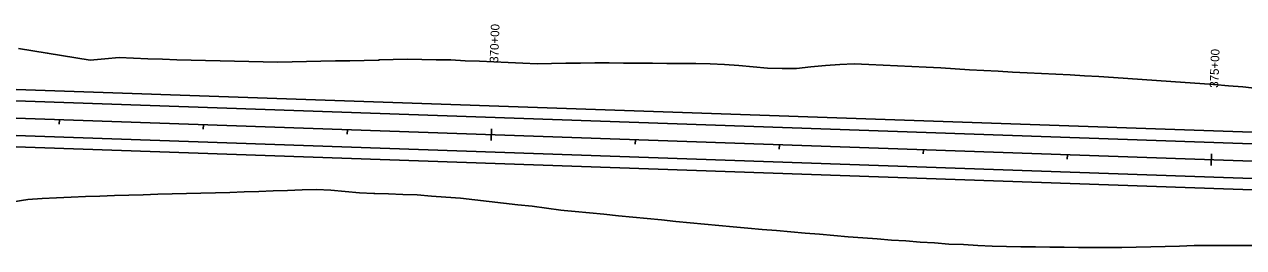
# Model space of a CAD drawing. Extents: x 881426 to 887360, y 1564404 to 1567430.
# Drawn here: x 885699 to 886545, y 1564418 to 1564573 of the extents above; entities that cross this region are included whole.
import ezdxf

# ---------------------------------------------------------------- set-up
doc = ezdxf.new("R2010")
doc.units = 0
for name, color, linetype in [('R_Horz Alg', 7, 'Continuous'), ('R_Horz Alg Annot', 7, 'Continuous'), ('R_Proposed Const Limits_Cut', 7, 'Continuous'), ('R_Proposed Const Limits_Fill', 7, 'Continuous'), ('R_Proposed Road_Lane', 7, 'Continuous'), ('R_Proposed Road_Shoulder', 7, 'Continuous')]:
    doc.layers.add(name, color=color, linetype=linetype)

msp = doc.modelspace()

# ---------------------------------------------------------------- linework, layer by layer
at = {"layer": 'R_Horz Alg'}
msp.add_line((885670.58, 1564508.69), (887357.73, 1564450.04), dxfattribs=at)
at = {"layer": 'R_Horz Alg Annot'}
for points in [[(885723.07, 1564503.86), (885723.17, 1564506.86)], [(885823.01, 1564500.39), (885823.11, 1564503.39)], [(885922.95, 1564496.91), (885923.05, 1564499.91)], [(886023.13, 1564500.43), (886022.85, 1564492.44)], [(886122.83, 1564489.96), (886122.93, 1564492.96)], [(886222.76, 1564486.49), (886222.87, 1564489.49)], [(886322.7, 1564483.02), (886322.81, 1564486.01)], [(886422.64, 1564479.54), (886422.75, 1564482.54)], [(886522.83, 1564483.06), (886522.55, 1564475.07)]]:
    msp.add_lwpolyline(points, dxfattribs=at)
at = {"layer": 'R_Proposed Const Limits_Cut'}
for points in [[(885744.62, 1564548.22), (885754.66, 1564549.23), (885764.69, 1564549.99), (885774.69, 1564549.57), (885784.68, 1564549.2), (885794.67, 1564548.85), (885804.67, 1564548.49), (885814.66, 1564548.2), (885824.66, 1564547.91), (885834.66, 1564547.67), (885844.65, 1564547.45), (885854.65, 1564547.22), (885864.65, 1564547.04), (885874.65, 1564546.94), (885884.67, 1564547.12), (885894.68, 1564547.31), (885904.69, 1564547.52), (885914.71, 1564547.72), (885924.72, 1564547.86), (885934.73, 1564548.02), (885944.75, 1564548.33), (885945.41, 1564548.35), (885954.76, 1564548.63), (885964.78, 1564548.94), (885974.78, 1564548.74), (885984.78, 1564548.54), (885994.78, 1564548.36), (886004.77, 1564547.88), (886014.76, 1564547.57), (886024.75, 1564547.13), (886034.74, 1564546.71), (886044.73, 1564546.22), (886054.72, 1564545.76), (886064.73, 1564545.84), (886074.74, 1564546.04), (886077.12, 1564546.07), (886084.76, 1564546.2), (886094.77, 1564546.33), (886104.77, 1564546.3), (886114.78, 1564546.24), (886124.78, 1564546.21), (886134.78, 1564546.14), (886144.79, 1564546.02), (886154.79, 1564545.95), (886164.79, 1564545.89), (886174.79, 1564545.64), (886184.78, 1564545.2), (886194.76, 1564544.41), (886204.74, 1564543.65), (886214.71, 1564542.68), (886224.71, 1564542.4), (886234.71, 1564542.38), (886244.76, 1564543.52), (886254.8, 1564544.47), (886264.83, 1564545.3), (886274.85, 1564545.69), (886284.84, 1564545.2), (886294.83, 1564544.79), (886304.82, 1564544.36), (886314.81, 1564543.81), (886324.8, 1564543.32), (886334.79, 1564542.81), (886344.77, 1564542.16), (886354.76, 1564541.58), (886364.75, 1564541.08), (886374.73, 1564540.48), (886384.72, 1564539.99), (886394.71, 1564539.54), (886404.7, 1564539.05), (886414.69, 1564538.55), (886424.68, 1564537.97), (886434.66, 1564537.35), (886444.65, 1564536.78), (886454.63, 1564536.19), (886464.61, 1564535.48), (886474.59, 1564534.78), (886484.58, 1564534.07), (886494.56, 1564533.41), (886504.54, 1564532.71), (886514.52, 1564531.98), (886524.5, 1564531.26), (886534.48, 1564530.5), (886544.46, 1564529.61), (886554.43, 1564528.56)], [(885901.59, 1564458.34), (885911.59, 1564457.94), (885921.56, 1564456.99), (885931.53, 1564456.04), (885941.52, 1564455.61), (885942.18, 1564455.59), (885951.52, 1564455.33), (885961.51, 1564454.94), (885971.5, 1564454.56), (885981.48, 1564453.77), (885991.46, 1564453.02), (886001.44, 1564452.25), (886011.41, 1564451.14), (886021.38, 1564450), (886031.34, 1564448.91), (886041.31, 1564447.78), (886051.28, 1564446.66), (886061.24, 1564445.37), (886071.2, 1564444.08), (886073.56, 1564443.79), (886081.17, 1564443.04), (886091.14, 1564442.06), (886101.11, 1564441.09), (886111.09, 1564440.11), (886121.06, 1564439.13), (886131.03, 1564438.16), (886141, 1564437.18), (886150.97, 1564436.2), (886160.95, 1564435.23), (886170.92, 1564434.25), (886180.89, 1564433.31), (886190.87, 1564432.4), (886200.84, 1564431.54), (886210.82, 1564430.64), (886220.79, 1564429.77), (886230.77, 1564428.9), (886240.74, 1564428.02), (886250.72, 1564427.19), (886260.7, 1564426.31), (886270.67, 1564425.49), (886280.65, 1564424.75), (886290.63, 1564424), (886300.61, 1564423.13), (886310.6, 1564422.58), (886320.57, 1564421.69), (886330.56, 1564421.22), (886340.54, 1564420.45), (886350.53, 1564420.01), (886360.52, 1564419.39), (886370.51, 1564418.94), (886380.51, 1564418.72), (886390.51, 1564418.59), (886400.51, 1564418.48), (886410.51, 1564418.33), (886420.51, 1564418.26), (886430.51, 1564418.1), (886440.52, 1564418.05), (886450.52, 1564417.93), (886460.53, 1564418.01), (886470.54, 1564418.15), (886480.56, 1564418.44), (886490.57, 1564418.77), (886500.59, 1564419.06), (886510.61, 1564419.37), (886520.61, 1564419.4), (886530.62, 1564419.35), (886540.62, 1564419.35), (886550.63, 1564419.33)]]:
    msp.add_lwpolyline(points, dxfattribs=at)
at = {"layer": 'R_Proposed Const Limits_Fill'}
for points in [[(885694.88, 1564556.43), (885704.82, 1564554.76), (885714.77, 1564553.14), (885724.72, 1564551.46), (885734.67, 1564549.75), (885744.62, 1564548.22)], [(885691.17, 1564449.84), (885701.23, 1564451.3), (885711.26, 1564452.13), (885721.28, 1564452.57), (885731.3, 1564452.99), (885741.32, 1564453.38), (885751.34, 1564453.71), (885761.36, 1564454.08), (885771.38, 1564454.42), (885781.4, 1564454.73), (885791.41, 1564455.06), (885801.43, 1564455.36), (885811.44, 1564455.61), (885821.46, 1564455.83), (885831.47, 1564456.04), (885841.49, 1564456.32), (885851.5, 1564456.65), (885861.52, 1564456.99), (885871.54, 1564457.33), (885881.56, 1564457.67), (885891.58, 1564458), (885901.59, 1564458.34)]]:
    msp.add_lwpolyline(points, dxfattribs=at)
at = {"layer": 'R_Proposed Road_Lane'}
for p, q in [((885670.99, 1564520.68), (887147.73, 1564469.34)), ((885670.16, 1564496.7), (887146.89, 1564445.36))]:
    msp.add_line(p, q, dxfattribs=at)
at = {"layer": 'R_Proposed Road_Shoulder'}
for p, q in [((885671.27, 1564528.68), (887148.01, 1564477.34)), ((885669.88, 1564488.7), (887146.62, 1564437.36))]:
    msp.add_line(p, q, dxfattribs=at)

# ---------------------------------------------------------------- texts
at = {"layer": 'R_Horz Alg Annot'}
for s, p in [('370+00', (886027.73, 1564546.3)), ('375+00', (886527.42, 1564528.93))]:
    msp.add_text(s, height=6, rotation=88.00892, dxfattribs=at).set_placement(p)

doc.saveas('drawing.dxf')
